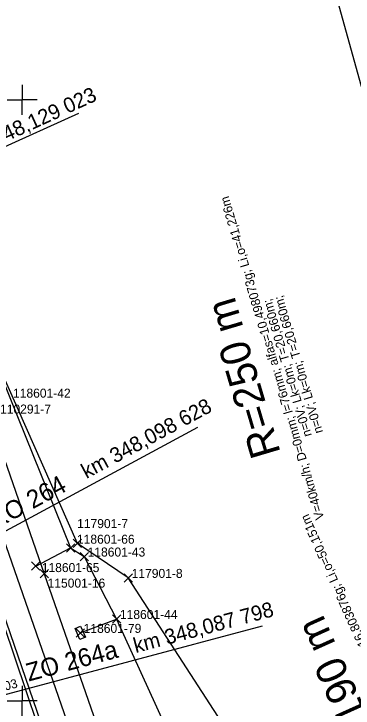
# Model space of a CAD drawing. Extents: x -821029 to -820632, y -1070881 to -1069931.
# Drawn here: x -820800.7 to -820772.5, y -1070400.6 to -1070342.9 of the extents above; entities that cross this region are included whole.
import ezdxf

# ---------------------------------------------------------------- set-up
doc = ezdxf.new("R2010")
doc.units = 0
for name, color, linetype in [('PS-11-02-31', 7, 'Continuous'), ('PS-11-02-41', 7, 'Continuous'), ('PS-11-02-92', 7, 'Continuous'), ('Ram', 7, 'Continuous'), ('Sit', 7, 'Continuous'), ('SO-11-10-01', 7, 'Continuous'), ('SO-11-31-01', 7, 'Continuous'), ('SO-11-50-01', 7, 'Continuous'), ('SO-11-79-01', 7, 'Continuous'), ('SO-11-86-01', 7, 'Continuous'), ('VB_PS-11-02-91', 7, 'Continuous'), ('VB_SO-11-10-01', 7, 'Continuous'), ('VB_SO-11-50-01', 7, 'Continuous'), ('VB_SO-11-79-01', 7, 'Continuous'), ('VB_SO-11-86-01', 7, 'Continuous')]:
    doc.layers.add(name, color=color, linetype=linetype)

msp = doc.modelspace()

# ---------------------------------------------------------------- linework, layer by layer
at = {"layer": 'PS-11-02-31'}
msp.add_line((-820795.17, -1070394.347), (-820792.153, -1070393.193), dxfattribs=at)
msp.add_lwpolyline([(-820834.739, -1070280.72), (-820830.77, -1070287.401), (-820826.598, -1070295.778), (-820822.74, -1070307.417), (-820822.402, -1070310.542), (-820820.817, -1070316.363), (-820815.079, -1070335.816), (-820806.043, -1070362.212), (-820801.047, -1070374.777), (-820795.979, -1070387.28), (-820794.84, -1070387.997), (-820792.153, -1070393.193), (-820783.482, -1070412.233), (-820783.598, -1070416.458), (-820783.598, -1070418.019), (-820782.431, -1070424.351)], dxfattribs=at)
msp.add_lwpolyline([(-820795.199, -1070394.906), (-820795.6, -1070393.99), (-820795.142, -1070393.789), (-820794.741, -1070394.705)], close=True, dxfattribs=at)
at = {"layer": 'PS-11-02-41'}
msp.add_lwpolyline([(-820882.988, -1070201.129), (-820875.537, -1070207.75), (-820872.787, -1070212.312), (-820866.572, -1070222.102), (-820863.695, -1070232.226), (-820854.155, -1070247.197), (-820844.785, -1070263.708), (-820834.739, -1070280.72), (-820830.77, -1070287.401), (-820826.598, -1070295.778), (-820822.74, -1070307.417), (-820822.402, -1070310.542), (-820820.817, -1070316.363), (-820815.079, -1070335.816), (-820806.043, -1070362.212), (-820801.047, -1070374.777), (-820795.979, -1070387.28), (-820794.84, -1070387.997), (-820792.153, -1070393.193), (-820783.482, -1070412.233), (-820783.598, -1070416.458), (-820783.598, -1070418.019), (-820782.431, -1070424.351)], dxfattribs=at)
at = {"layer": 'PS-11-02-92'}
msp.add_lwpolyline([(-820882.988, -1070201.129), (-820875.537, -1070207.75), (-820872.787, -1070212.312), (-820866.572, -1070222.102), (-820863.695, -1070232.226), (-820854.155, -1070247.197), (-820844.785, -1070263.708), (-820834.739, -1070280.72), (-820830.77, -1070287.401), (-820826.598, -1070295.778), (-820822.74, -1070307.417), (-820822.402, -1070310.542), (-820820.817, -1070316.363), (-820815.079, -1070335.816), (-820806.043, -1070362.212), (-820801.047, -1070374.777), (-820795.979, -1070387.28), (-820794.84, -1070387.997), (-820792.153, -1070393.193), (-820783.482, -1070412.233), (-820783.598, -1070416.458), (-820783.598, -1070418.019), (-820782.431, -1070424.351)], dxfattribs=at)
at = {"layer": 'Ram'}
msp.add_lwpolyline([(-820859.088, -1070034.797), (-820635.538, -1070839.316), (-820773.8, -1070877.734), (-820997.35, -1070073.215)], dxfattribs=at)
at = {"layer": 'Sit'}
for p, q in [((-820800, -1070348.75), (-820800, -1070350)), ((-820801.25, -1070350), (-820800, -1070350)), ((-820798.75, -1070350), (-820800, -1070350)), ((-820800, -1070351.25), (-820800, -1070350)), ((-820800, -1070398.75), (-820800, -1070400)), ((-820801.25, -1070400), (-820800, -1070400)), ((-820798.75, -1070400), (-820800, -1070400)), ((-820800, -1070401.25), (-820800, -1070400))]:
    msp.add_line(p, q, dxfattribs=at)
at = {"layer": 'SO-11-10-01'}
for p, q in [((-820795.329, -1070351.135), (-820818.089, -1070361.478)), ((-820785.407, -1070377.264), (-820811.823, -1070391.484)), ((-820780.049, -1070393.776), (-820804.198, -1070400.243))]:
    msp.add_line(p, q, dxfattribs=at)
at = {"layer": 'SO-11-31-01'}
for points in [[(-820926.07, -1070123.29), (-820916.95, -1070167.12), (-820908.61, -1070171.6), (-820902.99, -1070184.31), (-820895.92, -1070196.33), (-820868.5, -1070237.37), (-820845.66, -1070276.46), (-820841.66, -1070281.51), (-820839.82, -1070285.2), (-820808.13, -1070374.18), (-820790.33, -1070426.97), (-820782.93, -1070433.41), (-820769.19, -1070488.5), (-820779.762, -1070491.365)], [(-820832.57, -1070337.97), (-820821.56, -1070335.44), (-820813.99, -1070356.68), (-820798.47, -1070401.74), (-820795.5, -1070403.96), (-820793.85, -1070408.69), (-820790.57, -1070418.13), (-820788.93, -1070422.85), (-820783.27, -1070428.36), (-820780.97, -1070427.76), (-820780.24, -1070428.17), (-820779.88, -1070429.72), (-820781.01, -1070429.99)]]:
    msp.add_lwpolyline(points, dxfattribs=at)
at = {"layer": 'SO-11-50-01'}
for points in [[(-820831.742, -1070299.721), (-820794.486, -1070406.873), (-820788.19, -1070424.98)], [(-820815.774, -1070338.796), (-820798.172, -1070389.423), (-820789.142, -1070415.392), (-820782.756, -1070425.414), (-820778.113, -1070440.812), (-820778.3, -1070451.359), (-820766.965, -1070499.852)]]:
    msp.add_lwpolyline(points, dxfattribs=at)
at = {"layer": 'SO-11-79-01'}
msp.add_lwpolyline([(-820761.036, -1070511.475), (-820774.105, -1070459.005), (-820777.683, -1070442.395), (-820780.824, -1070405.778), (-820791.175, -1070389.775), (-820795.413, -1070386.908), (-820807.598, -1070359.392), (-820815.489, -1070325.838), (-820825.29, -1070295.054), (-820830.464, -1070283.216), (-820832.859, -1070278.435)], dxfattribs=at)
at = {"layer": 'SO-11-86-01'}
for p, q in [((-820798.874, -1070388.789), (-820795.979, -1070387.28)), ((-820795.17, -1070394.347), (-820792.153, -1070393.193))]:
    msp.add_line(p, q, dxfattribs=at)
msp.add_lwpolyline([(-820844.785, -1070263.708), (-820834.739, -1070280.72), (-820830.77, -1070287.401), (-820826.598, -1070295.778), (-820822.74, -1070307.417), (-820822.402, -1070310.542), (-820820.817, -1070316.363), (-820815.079, -1070335.816), (-820806.043, -1070362.212), (-820801.047, -1070374.777), (-820795.979, -1070387.28), (-820794.84, -1070387.997), (-820792.153, -1070393.193), (-820783.482, -1070412.233), (-820783.598, -1070416.458), (-820783.598, -1070418.019), (-820782.431, -1070424.351), (-820780.96, -1070434.384), (-820773.909, -1070463.726), (-820769.347, -1070482.633)], dxfattribs=at)
msp.add_lwpolyline([(-820795.199, -1070394.906), (-820795.6, -1070393.99), (-820795.142, -1070393.789), (-820794.741, -1070394.705)], close=True, dxfattribs=at)
at = {"layer": 'VB_SO-11-50-01'}
for p, q in [((-820798.516, -1070389.767), (-820797.828, -1070389.079)), ((-820797.828, -1070389.767), (-820798.516, -1070389.079))]:
    msp.add_line(p, q, dxfattribs=at)
at = {"layer": 'VB_SO-11-79-01'}
for p, q in [((-820795.757, -1070387.252), (-820795.069, -1070386.564)), ((-820795.069, -1070387.252), (-820795.757, -1070386.564)), ((-820791.519, -1070390.119), (-820790.831, -1070389.431)), ((-820790.831, -1070390.119), (-820791.519, -1070389.431))]:
    msp.add_line(p, q, dxfattribs=at)
at = {"layer": 'VB_SO-11-86-01'}
for p, q in [((-820796.323, -1070387.624), (-820795.635, -1070386.936)), ((-820795.635, -1070387.624), (-820796.323, -1070386.936)), ((-820795.184, -1070388.341), (-820794.496, -1070387.653)), ((-820794.496, -1070388.341), (-820795.184, -1070387.653)), ((-820799.218, -1070389.133), (-820798.53, -1070388.445)), ((-820798.53, -1070389.133), (-820799.218, -1070388.445)), ((-820792.497, -1070393.537), (-820791.809, -1070392.849)), ((-820791.809, -1070393.537), (-820792.497, -1070392.849)), ((-820795.514, -1070394.691), (-820794.826, -1070394.003)), ((-820794.826, -1070394.691), (-820795.514, -1070394.003))]:
    msp.add_line(p, q, dxfattribs=at)

# ---------------------------------------------------------------- texts
at = {"layer": 'SO-11-10-01'}
for s, height, rotation, p in [('km 348,129 023', 1.25, 24.43846, (-820804.613, -1070354.977)), ('V=40km/h; D=0mm; l=76mm; alfas=10,498073g; Li,o=41,226m', 0.75, 106.52801, (-820774.868, -1070384.813)), ('R=250 m', 2.5, 106.52801, (-820778.486, -1070379.359)), ('n=0V; Lk=0m; T=20,660m;', 0.75, 106.52801, (-820775.904, -1070377.909)), ('n=0V; Lk=0m; T=20,660m;', 0.75, 106.52801, (-820774.973, -1070377.633)), ('km 348,098 628', 1.25, 28.2952, (-820794.664, -1070381.554)), ('KO 264 ', 1.5, 28.2952, (-820802.182, -1070385.711)), ('V=40km/h; D=0mm; l=100mm; alfas=16,803876g; Li,o=50,151m', 0.75, 114.19329, (-820764.491, -1070410.46)), ('km 348,087 798', 1.25, 14.99064, (-820790.563, -1070396.034)), ('R=190 m', 2.5, 114.19329, (-820769.432, -1070405.179)), ('ZO 264a ', 1.5, 14.99064, (-820799.463, -1070398.396))]:
    msp.add_text(s, height=height, rotation=rotation, dxfattribs=at).set_placement(p)
at = {"layer": 'VB_PS-11-02-91'}
msp.add_text(' 110291-7', height=0.75, dxfattribs=at).set_placement((-820802.127, -1070376.103))
at = {"layer": 'VB_SO-11-10-01'}
msp.add_text('ZO=603', height=0.75, rotation=14.99064, dxfattribs=at).set_placement((-820803.857, -1070399.816))
at = {"layer": 'VB_SO-11-50-01'}
msp.add_text(' 115001-16', height=0.75, dxfattribs=at).set_placement((-820798.172, -1070390.579))
at = {"layer": 'VB_SO-11-79-01'}
for s, p in [(' 117901-7', (-820795.714, -1070385.631)), (' 117901-8', (-820791.175, -1070389.775))]:
    msp.add_text(s, height=0.75, dxfattribs=at).set_placement(p)
at = {"layer": 'VB_SO-11-86-01'}
for s, p in [(' 118601-42', (-820801.047, -1070374.777)), (' 118601-66', (-820795.728, -1070386.928)), (' 118601-43', (-820794.84, -1070387.997)), (' 118601-65', (-820798.656, -1070389.289)), (' 118601-44', (-820792.153, -1070393.193)), (' 118601-79', (-820795.17, -1070394.347))]:
    msp.add_text(s, height=0.75, dxfattribs=at).set_placement(p)

doc.saveas('drawing.dxf')
